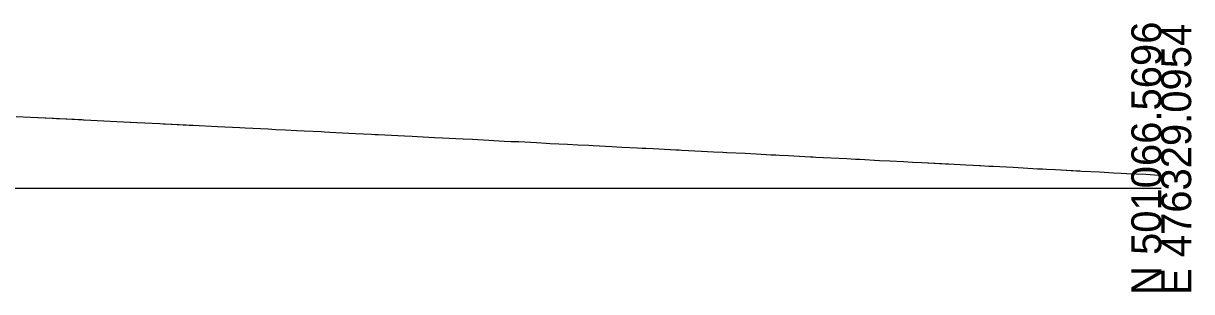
# Model space of a CAD drawing. Extents: x 78027 to 79855, y -93601 to -93005.
# Drawn here: x 78345.9 to 78455.3, y -93086.9 to -93061.8 of the extents above; entities that cross this region are included whole.
import ezdxf

# ---------------------------------------------------------------- set-up
doc = ezdxf.new("R2010")
doc.units = 0
for name, color, linetype in [('Exist Cross Section Cell', 7, 'Continuous'), ('Exist XS Ground Line', 7, 'Continuous'), ('Scratch_Level_0', 7, 'Continuous'), ('Scratch_Level_5', 7, 'Continuous'), ('Scratch_Level_6', 7, 'Continuous')]:
    doc.layers.add(name, color=color, linetype=linetype)

msp = doc.modelspace()

# ---------------------------------------------------------------- linework, layer by layer
at = {"layer": 'Exist Cross Section Cell'}
msp.add_line((78252.48, -93077.22), (78452.48, -93077.22), dxfattribs=at)
at = {"layer": 'Exist XS Ground Line'}
for p, q in [((78345.25, -93070.49), (78346.62, -93070.56)), ((78346.62, -93070.56), (78348.77, -93070.67)), ((78348.77, -93070.67), (78349.03, -93070.68)), ((78349.03, -93070.68), (78349.33, -93070.7)), ((78349.33, -93070.7), (78351.41, -93070.79)), ((78351.41, -93070.79), (78351.58, -93070.8)), ((78351.58, -93070.8), (78351.63, -93070.81)), ((78351.63, -93070.81), (78352.25, -93070.84)), ((78352.25, -93070.84), (78354.05, -93070.93)), ((78354.05, -93070.93), (78356.56, -93071.05)), ((78356.56, -93071.05), (78356.56, -93071.05)), ((78356.56, -93071.05), (78356.56, -93071.05)), ((78356.56, -93071.05), (78356.56, -93071.05)), ((78356.56, -93071.05), (78356.59, -93071.05)), ((78356.59, -93071.05), (78358.71, -93071.17)), ((78358.71, -93071.17), (78359.05, -93071.18)), ((78359.05, -93071.18), (78359.2, -93071.19)), ((78359.2, -93071.19), (78361.46, -93071.3)), ((78361.46, -93071.3), (78361.59, -93071.31)), ((78361.59, -93071.31), (78361.83, -93071.32)), ((78361.83, -93071.32), (78364.11, -93071.43)), ((78364.11, -93071.43), (78366.2, -93071.54)), ((78366.2, -93071.54), (78366.72, -93071.56)), ((78366.72, -93071.56), (78368.87, -93071.67)), ((78368.87, -93071.67), (78369.54, -93071.71)), ((78369.54, -93071.71), (78370.48, -93071.75)), ((78370.48, -93071.75), (78371.52, -93071.8)), ((78371.52, -93071.8), (78372.23, -93071.84)), ((78372.23, -93071.84), (78373.81, -93071.92)), ((78373.81, -93071.92), (78374.14, -93071.94)), ((78374.14, -93071.94), (78374.63, -93071.96)), ((78374.63, -93071.96), (78375.2, -93071.99)), ((78375.2, -93071.99), (78377.02, -93072.08)), ((78377.02, -93072.08), (78378.52, -93072.16)), ((78378.52, -93072.16), (78378.89, -93072.18)), ((78378.89, -93072.18), (78379.17, -93072.19)), ((78379.17, -93072.19), (78379.78, -93072.22)), ((78379.78, -93072.22), (78381.63, -93072.31)), ((78381.63, -93072.31), (78382.34, -93072.35)), ((78382.34, -93072.35), (78382.83, -93072.38)), ((78382.83, -93072.38), (78384.42, -93072.46)), ((78384.42, -93072.46), (78385.19, -93072.5)), ((78385.19, -93072.5), (78386.44, -93072.56)), ((78386.44, -93072.56), (78387.12, -93072.59)), ((78387.12, -93072.59), (78387.98, -93072.64)), ((78387.98, -93072.64), (78389.52, -93072.72)), ((78389.52, -93072.72), (78390.97, -93072.8)), ((78390.97, -93072.8), (78391.62, -93072.83)), ((78391.62, -93072.83), (78392.32, -93072.86)), ((78392.32, -93072.86), (78393.97, -93072.95)), ((78393.97, -93072.95), (78394.9, -93073)), ((78394.9, -93073), (78395.27, -93073.02)), ((78395.27, -93073.02), (78396.87, -93073.1)), ((78396.87, -93073.1), (78397.86, -93073.15)), ((78397.86, -93073.15), (78398.87, -93073.2)), ((78398.87, -93073.2), (78399.3, -93073.22)), ((78399.3, -93073.22), (78401.03, -93073.31)), ((78401.03, -93073.31), (78401.97, -93073.36)), ((78401.97, -93073.36), (78403.44, -93073.44)), ((78403.44, -93073.44), (78403.89, -93073.46)), ((78403.89, -93073.46), (78404.24, -93073.48)), ((78404.24, -93073.48), (78404.91, -93073.51)), ((78404.91, -93073.51), (78407.03, -93073.62)), ((78407.03, -93073.62), (78407.31, -93073.64)), ((78407.31, -93073.64), (78407.33, -93073.64)), ((78407.33, -93073.64), (78407.59, -93073.65)), ((78407.59, -93073.65), (78409.44, -93073.74)), ((78409.44, -93073.74), (78410.56, -93073.8)), ((78410.56, -93073.8), (78411.42, -93073.84)), ((78411.42, -93073.84), (78411.79, -93073.86)), ((78411.79, -93073.86), (78413.51, -93073.95)), ((78413.51, -93073.95), (78414.55, -93074.01)), ((78414.55, -93074.01), (78415.96, -93074.08)), ((78415.96, -93074.08), (78416.4, -93074.1)), ((78416.4, -93074.1), (78416.74, -93074.12)), ((78416.74, -93074.12), (78417.57, -93074.16)), ((78417.57, -93074.16), (78419.64, -93074.28)), ((78419.64, -93074.28), (78419.89, -93074.29)), ((78419.89, -93074.29), (78420.13, -93074.3)), ((78420.13, -93074.3), (78423.05, -93074.45)), ((78423.05, -93074.45), (78423.86, -93074.49)), ((78423.86, -93074.49), (78424.26, -93074.51)), ((78424.26, -93074.51), (78426.09, -93074.61)), ((78426.09, -93074.61), (78427.06, -93074.65)), ((78427.06, -93074.65), (78428.36, -93074.72)), ((78428.36, -93074.72), (78429.19, -93074.77)), ((78429.19, -93074.77), (78430.06, -93074.81)), ((78430.06, -93074.81), (78432.27, -93074.93)), ((78432.27, -93074.93), (78432.42, -93074.94)), ((78432.42, -93074.94), (78432.56, -93074.95)), ((78432.56, -93074.95), (78434.19, -93075.03)), ((78434.19, -93075.03), (78435.46, -93075.1)), ((78435.46, -93075.1), (78435.57, -93075.1)), ((78435.57, -93075.1), (78436.32, -93075.14)), ((78436.32, -93075.14), (78436.74, -93075.17)), ((78436.74, -93075.17), (78438.6, -93075.26)), ((78438.6, -93075.26), (78439.54, -93075.31)), ((78439.54, -93075.31), (78440.88, -93075.39)), ((78440.88, -93075.39), (78441.35, -93075.41)), ((78441.35, -93075.41), (78441.73, -93075.43)), ((78441.73, -93075.43), (78442.58, -93075.48)), ((78442.58, -93075.48), (78444.72, -93075.59)), ((78444.72, -93075.59), (78444.87, -93075.6)), ((78444.87, -93075.6), (78445.03, -93075.61)), ((78445.03, -93075.61), (78445.05, -93075.61)), ((78445.05, -93075.61), (78446.71, -93075.69)), ((78446.71, -93075.69), (78448.02, -93075.77)), ((78448.02, -93075.77), (78448.73, -93075.8)), ((78448.73, -93075.8), (78449.24, -93075.83)), ((78449.24, -93075.83), (78451.05, -93075.92)), ((78451.05, -93075.92), (78451.86, -93075.97)), ((78451.86, -93075.97), (78452.48, -93076))]:
    msp.add_line(p, q, dxfattribs=at)
at = {"layer": 'Scratch_Level_0'}
msp.add_lwpolyline([(78345.25, -93070.49), (78346.62, -93070.56), (78349.33, -93070.7), (78351.63, -93070.81), (78352.25, -93070.84), (78354.05, -93070.93), (78356.59, -93071.05), (78358.71, -93071.17), (78359.2, -93071.19), (78361.83, -93071.32), (78364.11, -93071.43), (78366.2, -93071.54), (78366.72, -93071.56), (78368.87, -93071.67), (78369.54, -93071.71), (78370.48, -93071.75), (78371.52, -93071.8), (78372.23, -93071.84), (78373.81, -93071.92), (78374.14, -93071.94), (78374.63, -93071.96), (78375.2, -93071.99), (78377.02, -93072.08), (78378.52, -93072.16), (78379.17, -93072.19), (78379.78, -93072.22), (78381.63, -93072.31), (78382.34, -93072.35), (78382.83, -93072.38), (78384.42, -93072.46), (78385.19, -93072.5), (78386.44, -93072.56), (78387.12, -93072.59), (78387.98, -93072.64), (78389.52, -93072.72), (78390.97, -93072.8), (78391.62, -93072.83), (78392.32, -93072.86), (78393.97, -93072.95), (78394.9, -93073), (78395.27, -93073.02), (78396.87, -93073.1), (78397.86, -93073.15), (78398.87, -93073.2), (78399.3, -93073.22), (78401.03, -93073.31), (78401.97, -93073.36), (78403.44, -93073.44), (78403.89, -93073.46), (78404.24, -93073.48), (78404.91, -93073.51), (78407.59, -93073.65), (78409.44, -93073.74), (78410.56, -93073.8), (78411.42, -93073.84), (78411.79, -93073.86), (78413.51, -93073.95), (78414.55, -93074.01), (78415.96, -93074.08), (78416.4, -93074.1), (78416.74, -93074.12), (78417.57, -93074.16), (78420.13, -93074.3), (78423.05, -93074.45), (78423.86, -93074.49), (78424.26, -93074.51), (78426.09, -93074.61), (78427.06, -93074.65), (78428.36, -93074.72), (78429.19, -93074.77), (78430.06, -93074.81), (78432.56, -93074.95), (78434.19, -93075.03), (78435.57, -93075.1), (78436.32, -93075.14), (78436.74, -93075.17), (78438.6, -93075.26), (78439.54, -93075.31), (78440.88, -93075.39), (78441.35, -93075.41), (78441.73, -93075.43), (78442.58, -93075.48), (78445.05, -93075.61), (78446.71, -93075.69), (78448.02, -93075.77), (78448.73, -93075.8), (78449.24, -93075.83), (78451.05, -93075.92), (78451.86, -93075.97), (78452.48, -93076)], dxfattribs=at)
at = {"layer": 'Scratch_Level_5'}
msp.add_lwpolyline([(78345.25, -93070.49), (78346.62, -93070.56), (78349.33, -93070.7), (78351.63, -93070.81), (78352.25, -93070.84), (78354.05, -93070.93), (78356.59, -93071.05), (78358.71, -93071.17), (78359.2, -93071.19), (78361.83, -93071.32), (78364.11, -93071.43), (78366.2, -93071.54), (78366.72, -93071.56), (78368.87, -93071.67), (78369.54, -93071.71), (78370.48, -93071.75), (78371.52, -93071.8), (78372.23, -93071.84), (78373.81, -93071.92), (78374.14, -93071.94), (78374.63, -93071.96), (78375.2, -93071.99), (78377.02, -93072.08), (78378.52, -93072.16), (78379.17, -93072.19), (78379.78, -93072.22), (78381.63, -93072.31), (78382.34, -93072.35), (78382.83, -93072.38), (78384.42, -93072.46), (78385.19, -93072.5), (78386.44, -93072.56), (78387.12, -93072.59), (78387.98, -93072.64), (78389.52, -93072.72), (78390.97, -93072.8), (78391.62, -93072.83), (78392.32, -93072.86), (78393.97, -93072.95), (78394.9, -93073), (78395.27, -93073.02), (78396.87, -93073.1), (78397.86, -93073.15), (78398.87, -93073.2), (78399.3, -93073.22), (78401.03, -93073.31), (78401.97, -93073.36), (78403.44, -93073.44), (78403.89, -93073.46), (78404.24, -93073.48), (78404.91, -93073.51), (78407.59, -93073.65), (78409.44, -93073.74), (78410.56, -93073.8), (78411.42, -93073.84), (78411.79, -93073.86), (78413.51, -93073.95), (78414.55, -93074.01), (78415.96, -93074.08), (78416.4, -93074.1), (78416.74, -93074.12), (78417.57, -93074.16), (78420.13, -93074.3), (78423.05, -93074.45), (78423.86, -93074.49), (78424.26, -93074.51), (78426.09, -93074.61), (78427.06, -93074.65), (78428.36, -93074.72), (78429.19, -93074.77), (78430.06, -93074.81), (78432.56, -93074.95), (78434.19, -93075.03), (78435.57, -93075.1), (78436.32, -93075.14), (78436.74, -93075.17), (78438.6, -93075.26), (78439.54, -93075.31), (78440.88, -93075.39), (78441.35, -93075.41), (78441.73, -93075.43), (78442.58, -93075.48), (78445.05, -93075.61), (78446.71, -93075.69), (78448.02, -93075.77), (78448.73, -93075.8), (78449.24, -93075.83), (78451.05, -93075.92), (78451.86, -93075.97), (78452.48, -93076)], dxfattribs=at)
at = {"layer": 'Scratch_Level_6'}
msp.add_lwpolyline([(78345.25, -93070.49), (78346.62, -93070.56), (78349.33, -93070.7), (78351.63, -93070.81), (78352.25, -93070.84), (78354.05, -93070.93), (78356.59, -93071.05), (78358.71, -93071.17), (78359.2, -93071.19), (78361.83, -93071.32), (78364.11, -93071.43), (78366.2, -93071.54), (78366.72, -93071.56), (78368.87, -93071.67), (78369.54, -93071.71), (78370.48, -93071.75), (78371.52, -93071.8), (78372.23, -93071.84), (78373.81, -93071.92), (78374.14, -93071.94), (78374.63, -93071.96), (78375.2, -93071.99), (78377.02, -93072.08), (78378.52, -93072.16), (78379.17, -93072.19), (78379.78, -93072.22), (78381.63, -93072.31), (78382.34, -93072.35), (78382.83, -93072.38), (78384.42, -93072.46), (78385.19, -93072.5), (78386.44, -93072.56), (78387.12, -93072.59), (78387.98, -93072.64), (78389.52, -93072.72), (78390.97, -93072.8), (78391.62, -93072.83), (78392.32, -93072.86), (78393.97, -93072.95), (78394.9, -93073), (78395.27, -93073.02), (78396.87, -93073.1), (78397.86, -93073.15), (78398.87, -93073.2), (78399.3, -93073.22), (78401.03, -93073.31), (78401.97, -93073.36), (78403.44, -93073.44), (78403.89, -93073.46), (78404.24, -93073.48), (78404.91, -93073.51), (78407.59, -93073.65), (78409.44, -93073.74), (78410.56, -93073.8), (78411.42, -93073.84), (78411.79, -93073.86), (78413.51, -93073.95), (78414.55, -93074.01), (78415.96, -93074.08), (78416.4, -93074.1), (78416.74, -93074.12), (78417.57, -93074.16), (78420.13, -93074.3), (78423.05, -93074.45), (78423.86, -93074.49), (78424.26, -93074.51), (78426.09, -93074.61), (78427.06, -93074.65), (78428.36, -93074.72), (78429.19, -93074.77), (78430.06, -93074.81), (78432.56, -93074.95), (78434.19, -93075.03), (78435.57, -93075.1), (78436.32, -93075.14), (78436.74, -93075.17), (78438.6, -93075.26), (78439.54, -93075.31), (78440.88, -93075.39), (78441.35, -93075.41), (78441.73, -93075.43), (78442.58, -93075.48), (78445.05, -93075.61), (78446.71, -93075.69), (78448.02, -93075.77), (78448.73, -93075.8), (78449.24, -93075.83), (78451.05, -93075.92), (78451.86, -93075.97), (78452.48, -93076)], dxfattribs=at)

# ---------------------------------------------------------------- texts
at = {"layer": 'Exist Cross Section Cell'}
for s, p in [('N 501066.5696', (78452.48, -93087.22)), ('E 476329.0954', (78455.28, -93087.22))]:
    msp.add_text(s, height=2.8, rotation=90, dxfattribs=at).set_placement(p)

doc.saveas('drawing.dxf')
